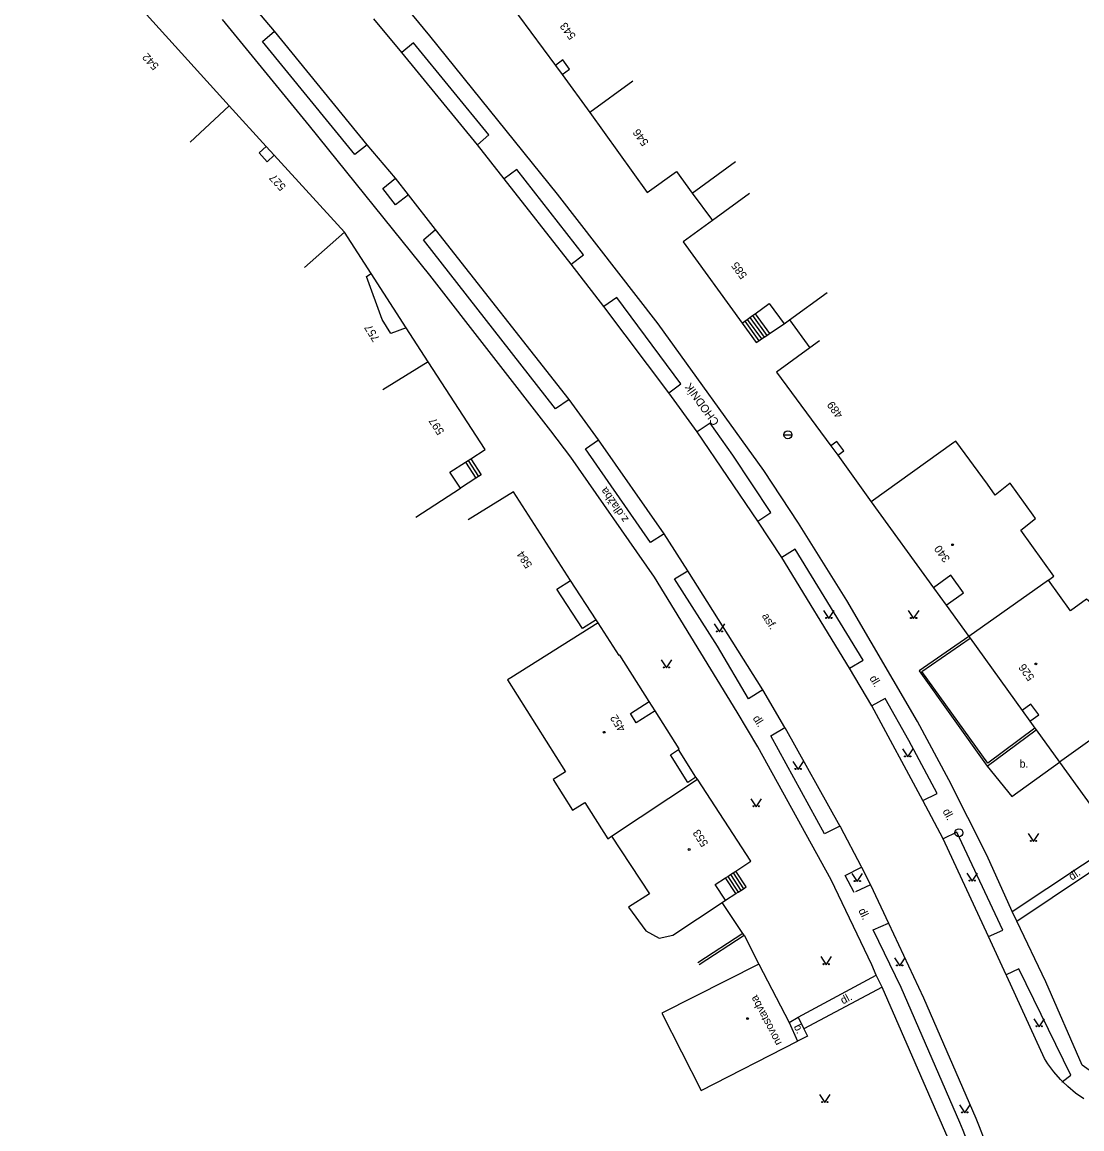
# Model space of a CAD drawing. Extents: x -536391 to -535419, y -1201788 to -1200779.
# Drawn here: x -535647.8 to -535548.5, y -1201544.3 to -1201440.5 of the extents above; entities that cross this region are included whole.
import ezdxf

# ---------------------------------------------------------------- set-up
doc = ezdxf.new("R2010")
doc.units = 0
for name, color, linetype in [('CIZÍ_NADZEM_POPIS', 7, 'Continuous'), ('CIZÍ_PODZEM', 7, 'Continuous'), ('CIZÍ_PODZEM_POPIS', 7, 'Continuous'), ('ELE_EON', 7, 'Continuous'), ('POL_ZNAČKA_PRACOVNÍ', 7, 'Continuous'), ('SDEL_EON', 7, 'Continuous'), ('SDEL_EON_POPIS', 7, 'Continuous'), ('TECH_OCHR_PÁSMO_HRAN', 7, 'Continuous'), ('ZP_EON', 7, 'Continuous')]:
    doc.layers.add(name, color=color, linetype=linetype)

msp = doc.modelspace()

# ---------------------------------------------------------------- linework, layer by layer
at = {"layer": 'CIZÍ_PODZEM'}
for centre in [(-535560.63, -1201489.51), (-535552.83, -1201500.69), (-535593.29, -1201507.09), (-535585.32, -1201518.08), (-535579.84, -1201533.93)]:
    msp.add_circle(centre, 0.0875, dxfattribs=at)
at = {"layer": 'CIZÍ_PODZEM_POPIS'}
msp.add_line((-535576.445, -1201479.21), (-535575.695, -1201479.21), dxfattribs=at)
for points in [[(-535585.02, -1201456.55), (-535583.14, -1201459.14)], [(-535575.91, -1201468.43), (-535574, -1201471.06)], [(-535559.12, -1201498.12), (-535563.78, -1201501.34), (-535557.38, -1201510.26), (-535552.8, -1201506.87)], [(-535552.92, -1201506.71), (-535557.33, -1201509.98), (-535563.5, -1201501.39), (-535559, -1201498.28)], [(-535580.3, -1201525.96), (-535582.22, -1201523.03)], [(-535580.3, -1201525.96), (-535584.49, -1201528.69)], [(-535584.38, -1201528.86), (-535580.16, -1201526.11), (-535580.3, -1201525.96)], [(-535580.16, -1201526.11), (-535578.8, -1201528.82)]]:
    msp.add_lwpolyline(points, dxfattribs=at)
msp.add_circle((-535576.07, -1201479.21), 0.375, dxfattribs=at)
at = {"layer": 'ELE_EON'}
for radius in [0.375, 0.0005]:
    msp.add_circle((-535560.04, -1201516.511), radius, dxfattribs=at)
at = {"layer": 'SDEL_EON'}
for points in [[(-535572.72, -1201495.68), (-535572.22, -1201496.43), (-535571.72, -1201495.68)], [(-535564.78, -1201495.68), (-535564.28, -1201496.43), (-535563.78, -1201495.68)], [(-535582.98, -1201496.94), (-535582.48, -1201497.69), (-535581.98, -1201496.94)], [(-535587.95, -1201500.31), (-535587.45, -1201501.06), (-535586.95, -1201500.31)], [(-535565.34, -1201508.65), (-535564.84, -1201509.4), (-535564.34, -1201508.65)], [(-535575.61, -1201509.83), (-535575.11, -1201510.58), (-535574.61, -1201509.83)], [(-535579.54, -1201513.32), (-535579.04, -1201514.07), (-535578.54, -1201513.32)], [(-535553.54, -1201516.57), (-535553.04, -1201517.32), (-535552.54, -1201516.57)], [(-535570.06, -1201520.34), (-535569.56, -1201521.09), (-535569.06, -1201520.34)], [(-535559.29, -1201520.29), (-535558.79, -1201521.04), (-535558.29, -1201520.29)], [(-535572.99, -1201528.12), (-535572.49, -1201528.87), (-535571.99, -1201528.12)], [(-535566.09, -1201528.24), (-535565.59, -1201528.99), (-535565.09, -1201528.24)], [(-535553.03, -1201533.94), (-535552.53, -1201534.69), (-535552.03, -1201533.94)], [(-535573.11, -1201541.05), (-535572.61, -1201541.8), (-535572.11, -1201541.05)], [(-535559.99, -1201542.01), (-535559.49, -1201542.76), (-535558.99, -1201542.01)]]:
    msp.add_lwpolyline(points, dxfattribs=at)
for centre in [(-535572.47, -1201496.38), (-535571.97, -1201496.38), (-535564.53, -1201496.38), (-535564.03, -1201496.38), (-535582.73, -1201497.64), (-535582.23, -1201497.64), (-535587.7, -1201501.01), (-535587.2, -1201501.01), (-535565.09, -1201509.35), (-535564.59, -1201509.35), (-535575.36, -1201510.53), (-535574.86, -1201510.53), (-535579.29, -1201514.02), (-535578.79, -1201514.02), (-535553.29, -1201517.27), (-535552.79, -1201517.27), (-535569.81, -1201521.04), (-535569.31, -1201521.04), (-535559.04, -1201520.99), (-535558.54, -1201520.99), (-535572.74, -1201528.82), (-535572.24, -1201528.82), (-535565.84, -1201528.94), (-535565.34, -1201528.94), (-535552.78, -1201534.64), (-535552.28, -1201534.64), (-535572.86, -1201541.75), (-535572.36, -1201541.75), (-535559.74, -1201542.71), (-535559.24, -1201542.71)]:
    msp.add_circle(centre, 0.05, dxfattribs=at)
at = {"layer": 'SDEL_EON_POPIS'}
for points in [[(-535603.63, -1201436.76), (-535597.84, -1201444.59)], [(-535628.43, -1201448.37), (-535636.18, -1201439.82)], [(-535597.22, -1201445.45), (-535596.52, -1201444.93), (-535597.16, -1201444.08), (-535597.84, -1201444.59)], [(-535597.84, -1201444.59), (-535597.22, -1201445.45)], [(-535597.22, -1201445.45), (-535594.64, -1201449.01)], [(-535590.58, -1201446.08), (-535594.64, -1201449.01)], [(-535628.43, -1201448.37), (-535632.07, -1201451.79)], [(-535624.94, -1201452.19), (-535628.43, -1201448.37)], [(-535594.64, -1201449.01), (-535589.26, -1201456.5), (-535586.5, -1201454.52), (-535585.02, -1201456.55)], [(-535624.19, -1201453.01), (-535624.85, -1201453.62), (-535625.61, -1201452.79), (-535624.94, -1201452.19)], [(-535624.19, -1201453.01), (-535624.94, -1201452.19)], [(-535617.62, -1201460.22), (-535624.19, -1201453.01)], [(-535585.02, -1201456.55), (-535580.97, -1201453.61)], [(-535579.65, -1201456.6), (-535583.14, -1201459.14)], [(-535583.14, -1201459.14), (-535585.89, -1201461.14), (-535580.35, -1201468.74)], [(-535617.62, -1201460.22), (-535621.36, -1201463.53)], [(-535615.13, -1201464.09), (-535617.62, -1201460.22)], [(-535611.83, -1201469.2), (-535613.28, -1201469.71), (-535614.09, -1201468.41), (-535615.54, -1201464.37), (-535615.13, -1201464.09)], [(-535611.83, -1201469.2), (-535615.13, -1201464.09)], [(-535575.91, -1201468.43), (-535572.39, -1201465.87)], [(-535579.14, -1201467.86), (-535577.82, -1201466.9), (-535576.43, -1201468.81)], [(-535579.38, -1201468.04), (-535579.14, -1201467.86)], [(-535580.35, -1201468.74), (-535580.11, -1201468.57)], [(-535580.11, -1201468.57), (-535579.87, -1201468.39)], [(-535579.87, -1201468.39), (-535579.62, -1201468.21)], [(-535579.62, -1201468.21), (-535579.38, -1201468.04)], [(-535576.43, -1201468.81), (-535575.91, -1201468.43)], [(-535609.77, -1201472.37), (-535611.83, -1201469.2)], [(-535574, -1201471.06), (-535577.13, -1201473.34), (-535572.04, -1201480.25)], [(-535573.09, -1201470.39), (-535574, -1201471.06)], [(-535609.77, -1201472.37), (-535614.02, -1201475)], [(-535605.77, -1201481.45), (-535604.43, -1201480.58), (-535609.77, -1201472.37)], [(-535571.38, -1201481.13), (-535570.82, -1201480.7), (-535571.48, -1201479.84), (-535572.04, -1201480.25)], [(-535572.04, -1201480.25), (-535571.38, -1201481.13)], [(-535571.38, -1201481.13), (-535568.27, -1201485.48)], [(-535606.75, -1201484.22), (-535607.73, -1201482.72), (-535606.27, -1201481.77)], [(-535606.27, -1201481.77), (-535606.02, -1201481.61)], [(-535606.02, -1201481.61), (-535605.77, -1201481.45)], [(-535610.94, -1201486.94), (-535606.75, -1201484.22)], [(-535596.43, -1201492.88), (-535601.78, -1201484.55), (-535606.03, -1201487.18)], [(-535568.27, -1201485.48), (-535562.42, -1201493.56)], [(-535561.25, -1201495.18), (-535559.62, -1201494.01), (-535560.8, -1201492.38), (-535562.42, -1201493.56)], [(-535594.02, -1201496.55), (-535595.31, -1201497.36), (-535597.73, -1201493.68), (-535596.43, -1201492.88)], [(-535594.02, -1201496.55), (-535596.43, -1201492.88)], [(-535562.42, -1201493.56), (-535561.25, -1201495.18)], [(-535561.25, -1201495.18), (-535559.12, -1201498.12)], [(-535593.84, -1201496.84), (-535594.02, -1201496.55)], [(-535589.05, -1201504.22), (-535591.81, -1201499.86), (-535591.89, -1201499.91), (-535593.84, -1201496.84)], [(-535559.12, -1201498.12), (-535559, -1201498.28)], [(-535559, -1201498.28), (-535554.1, -1201505.06)], [(-535588.51, -1201505.08), (-535590.27, -1201506.19), (-535590.81, -1201505.33), (-535589.05, -1201504.22)], [(-535588.51, -1201505.08), (-535589.05, -1201504.22)], [(-535586.31, -1201508.69), (-535586.24, -1201508.64), (-535588.51, -1201505.08)], [(-535553.38, -1201506.06), (-535552.56, -1201505.47), (-535553.29, -1201504.47), (-535554.1, -1201505.06)], [(-535554.1, -1201505.06), (-535553.38, -1201506.06)], [(-535553.38, -1201506.06), (-535552.92, -1201506.71)], [(-535552.92, -1201506.71), (-535552.8, -1201506.87)], [(-535552.8, -1201506.87), (-535550.61, -1201509.88)], [(-535584.69, -1201511.3), (-535585.45, -1201511.8), (-535587.08, -1201509.19), (-535586.31, -1201508.69)], [(-535584.69, -1201511.3), (-535586.31, -1201508.69)], [(-535550.61, -1201509.88), (-535545.22, -1201517.36), (-535542.59, -1201515.46), (-535539.52, -1201519.7)], [(-535584.55, -1201511.49), (-535584.69, -1201511.3)], [(-535580.95, -1201520.11), (-535579.53, -1201519.18), (-535584.55, -1201511.49)], [(-535581.92, -1201522.84), (-535582.88, -1201521.36), (-535581.92, -1201520.74)], [(-535581.92, -1201520.74), (-535581.7, -1201520.6)], [(-535581.7, -1201520.6), (-535581.45, -1201520.43)], [(-535581.45, -1201520.43), (-535581.2, -1201520.27)], [(-535581.2, -1201520.27), (-535580.95, -1201520.11)], [(-535582.22, -1201523.03), (-535581.92, -1201522.84)], [(-535578.8, -1201528.82), (-535575.96, -1201534.28), (-535575.17, -1201536.03)]]:
    msp.add_lwpolyline(points, dxfattribs=at)
at = {"layer": 'TECH_OCHR_PÁSMO_HRAN'}
for points in [[(-535575.08, -1201487.48), (-535578.32, -1201482.57), (-535588.21, -1201468.81), (-535597.64, -1201456.65), (-535609.61, -1201441.81), (-535625.68, -1201422.33), (-535639.79, -1201405.22), (-535649.04, -1201393.87), (-535654.09, -1201387.48), (-535663.33, -1201375.03), (-535670.67, -1201364.48), (-535678.2, -1201352.8), (-535684.64, -1201342.15), (-535696.74, -1201321.29), (-535703.13, -1201310.59)], [(-535624.17, -1201441.38), (-535626.81, -1201438.25)], [(-535588.58, -1201492.55), (-535596.39, -1201481.31), (-535598.27, -1201478.84), (-535609.61, -1201464.24), (-535620.89, -1201450.25), (-535629.06, -1201440.29)], [(-535612.25, -1201443.38), (-535614.85, -1201440.24)], [(-535615.48, -1201452.05), (-535616.66, -1201452.93), (-535625.31, -1201442.34), (-535624.17, -1201441.38)], [(-535615.48, -1201452.05), (-535624.17, -1201441.38)], [(-535605.16, -1201452.04), (-535604.1, -1201451.1), (-535611.16, -1201442.48), (-535612.25, -1201443.38)], [(-535605.16, -1201452.04), (-535612.25, -1201443.38)], [(-535612.84, -1201455.15), (-535615.48, -1201452.05)], [(-535602.64, -1201455.23), (-535605.16, -1201452.04)], [(-535596.38, -1201463.21), (-535595.22, -1201462.35), (-535601.47, -1201454.35), (-535602.64, -1201455.23)], [(-535611.62, -1201456.73), (-535612.83, -1201457.65), (-535614.02, -1201456.12), (-535612.84, -1201455.15)], [(-535611.62, -1201456.73), (-535612.84, -1201455.15)], [(-535596.38, -1201463.21), (-535602.64, -1201455.23)], [(-535609.08, -1201459.97), (-535611.62, -1201456.73)], [(-535596.57, -1201475.91), (-535597.83, -1201476.77), (-535610.22, -1201460.94), (-535609.08, -1201459.97)], [(-535596.57, -1201475.91), (-535609.08, -1201459.97)], [(-535593.31, -1201467.2), (-535596.38, -1201463.21)], [(-535587.22, -1201475.27), (-535586.09, -1201474.42), (-535592.1, -1201466.35), (-535593.31, -1201467.2)], [(-535587.22, -1201475.27), (-535593.31, -1201467.2)], [(-535579.14, -1201467.86), (-535577.78, -1201469.72)], [(-535580.35, -1201468.74), (-535579.03, -1201470.56), (-535578.78, -1201470.39)], [(-535580.11, -1201468.57), (-535578.78, -1201470.39)], [(-535579.87, -1201468.39), (-535578.53, -1201470.22)], [(-535579.62, -1201468.21), (-535578.28, -1201470.05)], [(-535579.38, -1201468.04), (-535578.03, -1201469.89)], [(-535577.78, -1201469.72), (-535576.43, -1201468.81)], [(-535578.28, -1201470.05), (-535578.03, -1201469.89)], [(-535578.03, -1201469.89), (-535577.78, -1201469.72)], [(-535578.78, -1201470.39), (-535578.53, -1201470.22)], [(-535578.53, -1201470.22), (-535578.28, -1201470.05)], [(-535593.82, -1201479.68), (-535596.57, -1201475.91)], [(-535584.56, -1201478.93), (-535587.22, -1201475.27)], [(-535578.87, -1201487.3), (-535577.65, -1201486.49), (-535581.22, -1201481.13), (-535583.35, -1201478.13), (-535584.56, -1201478.93)], [(-535578.87, -1201487.3), (-535584.56, -1201478.93)], [(-535587.67, -1201488.49), (-535588.95, -1201489.29), (-535595.03, -1201480.53), (-535593.82, -1201479.68)], [(-535587.67, -1201488.49), (-535593.82, -1201479.68)], [(-535606.27, -1201481.77), (-535605.3, -1201483.28)], [(-535606.02, -1201481.61), (-535605.05, -1201483.11)], [(-535605.77, -1201481.45), (-535604.8, -1201482.95), (-535605.05, -1201483.11)], [(-535605.3, -1201483.28), (-535606.75, -1201484.22)], [(-535605.05, -1201483.11), (-535605.3, -1201483.28)], [(-535576.64, -1201490.71), (-535578.87, -1201487.3)], [(-535555.04, -1201523.88), (-535557.42, -1201518.6), (-535560.98, -1201511.54), (-535563.92, -1201506.08), (-535570.55, -1201494.73), (-535575.08, -1201487.48)], [(-535585.45, -1201491.95), (-535587.67, -1201488.49)], [(-535570.28, -1201501.09), (-535569.02, -1201500.34), (-535575.39, -1201489.94), (-535576.64, -1201490.71)], [(-535570.28, -1201501.09), (-535576.64, -1201490.71)], [(-535559.28, -1201549.57), (-535559.59, -1201548.75), (-535561.04, -1201545.16), (-535567.24, -1201530.99), (-535567.78, -1201529.85), (-535568.21, -1201528.88), (-535572, -1201520.91), (-535578.88, -1201508.46), (-535580.82, -1201505.2), (-535588.58, -1201492.55)], [(-535578.4, -1201503.1), (-535579.76, -1201503.95), (-535582.65, -1201499.03), (-535586.68, -1201492.71), (-535585.45, -1201491.95)], [(-535578.4, -1201503.1), (-535585.45, -1201491.95)], [(-535568.2, -1201504.62), (-535570.28, -1201501.09)], [(-535576.34, -1201506.64), (-535578.4, -1201503.1)], [(-535563.41, -1201513.48), (-535562.09, -1201512.83), (-535564.73, -1201507.85), (-535566.94, -1201503.92), (-535568.2, -1201504.62)], [(-535563.41, -1201513.48), (-535568.2, -1201504.62)], [(-535571.19, -1201515.88), (-535572.62, -1201516.6), (-535577.66, -1201507.41), (-535576.34, -1201506.64)], [(-535576.34, -1201506.64), (-535571.19, -1201515.88)], [(-535557.38, -1201510.26), (-535555.08, -1201513.12), (-535550.61, -1201509.88)], [(-535561.52, -1201517.09), (-535563.41, -1201513.48)], [(-535571.19, -1201515.88), (-535571.13, -1201515.99), (-535569.22, -1201519.6), (-535569.16, -1201519.73)], [(-535557.26, -1201526.23), (-535555.94, -1201525.63), (-535560.22, -1201516.46), (-535561.52, -1201517.09)], [(-535557.26, -1201526.23), (-535561.52, -1201517.09)], [(-535555.04, -1201523.88), (-535545.22, -1201517.36)], [(-535554.6, -1201524.8), (-535544.59, -1201518.09), (-535542.21, -1201521.62)], [(-535569.87, -1201522.11), (-535570.69, -1201520.51), (-535569.16, -1201519.73)], [(-535569.16, -1201519.73), (-535568.34, -1201521.39)], [(-535580.95, -1201522.21), (-535581.92, -1201520.74)], [(-535581.7, -1201520.6), (-535580.74, -1201522.07)], [(-535581.45, -1201520.43), (-535580.49, -1201521.91)], [(-535581.2, -1201520.27), (-535580.24, -1201521.75)], [(-535580.24, -1201521.75), (-535579.99, -1201521.58), (-535580.95, -1201520.11)], [(-535580.49, -1201521.91), (-535580.24, -1201521.75)], [(-535568.34, -1201521.39), (-535569.73, -1201522.04)], [(-535568.34, -1201521.39), (-535566.65, -1201524.99)], [(-535581.92, -1201522.84), (-535580.95, -1201522.21)], [(-535580.95, -1201522.21), (-535580.74, -1201522.07)], [(-535580.74, -1201522.07), (-535580.49, -1201521.91)], [(-535554.6, -1201524.8), (-535555.04, -1201523.88)], [(-535568.06, -1201525.62), (-535566.65, -1201524.99)], [(-535566.65, -1201524.99), (-535563.37, -1201531.99), (-535558.46, -1201543.26), (-535558.14, -1201544.05), (-535556.54, -1201548.16)], [(-535533.37, -1201535.56), (-535539.82, -1201539.32), (-535539.9, -1201539.36), (-535540.68, -1201539.65), (-535541.47, -1201539.86), (-535542.29, -1201540), (-535543.11, -1201540.06), (-535543.94, -1201540.03), (-535544.76, -1201539.93), (-535545.56, -1201539.75), (-535546.35, -1201539.49), (-535547.1, -1201539.16), (-535547.82, -1201538.75), (-535548.5, -1201538.28), (-535551.9, -1201530.48), (-535554.6, -1201524.8)], [(-535557.96, -1201548.78), (-535558.09, -1201548.43), (-535559.64, -1201544.42), (-535559.94, -1201543.67), (-535565.46, -1201531.02), (-535568.06, -1201525.62)], [(-535555.61, -1201529.83), (-535557.26, -1201526.23)], [(-535575.96, -1201534.28), (-535575.11, -1201533.79), (-535567.78, -1201529.85)], [(-535550.33, -1201539.83), (-535549.54, -1201539.23), (-535554.43, -1201529.26), (-535555.61, -1201529.83)], [(-535550.33, -1201539.83), (-535550.53, -1201539.64), (-535551.15, -1201538.92), (-535551.71, -1201538.16), (-535552.02, -1201537.67), (-535555.55, -1201529.95), (-535555.61, -1201529.83)], [(-535567.24, -1201530.99), (-535574.57, -1201534.88), (-535574.24, -1201535.57), (-535575.17, -1201536.03)], [(-535575.11, -1201533.79), (-535574.57, -1201534.88)], [(-535550.38, -1201539.87), (-535550.33, -1201539.83)], [(-535548.32, -1201541.43), (-535549.11, -1201540.9), (-535549.84, -1201540.3), (-535550.33, -1201539.83)]]:
    msp.add_lwpolyline(points, dxfattribs=at)
at = {"layer": 'ZP_EON'}
for points in [[(-535551.65, -1201492.83), (-535551.14, -1201492.47), (-535554.25, -1201488.16), (-535552.86, -1201487.04), (-535553.07, -1201486.75), (-535555.24, -1201483.74), (-535556.63, -1201484.86), (-535557.37, -1201483.85), (-535560.34, -1201479.81), (-535560.52, -1201479.94), (-535568.27, -1201485.48)], [(-535543.17, -1201504.58), (-535545.22, -1201501.82), (-535543.66, -1201500.66), (-535545.15, -1201497.07), (-535548.08, -1201494.6), (-535549.58, -1201495.71), (-535551.65, -1201492.83), (-535559.12, -1201498.12)], [(-535593.84, -1201496.84), (-535602.03, -1201502), (-535602.34, -1201502.19), (-535596.91, -1201510.8), (-535598.05, -1201511.52), (-535596.25, -1201514.39), (-535595.1, -1201513.67), (-535592.95, -1201517.08), (-535592.58, -1201516.84), (-535584.55, -1201511.49)], [(-535533.86, -1201516), (-535536.09, -1201512.79), (-535536.93, -1201513.39), (-535540.05, -1201508.98), (-535530.66, -1201502.35), (-535533.84, -1201498.06), (-535543.17, -1201504.58), (-535550.61, -1201509.88)], [(-535592.58, -1201516.84), (-535589.04, -1201522.22), (-535590.99, -1201523.49), (-535589.38, -1201525.7), (-535588.14, -1201526.4), (-535586.84, -1201526.12), (-535582.22, -1201523.03)], [(-535578.8, -1201528.82), (-535587.87, -1201533.43), (-535584.2, -1201540.65), (-535575.17, -1201536.03)]]:
    msp.add_lwpolyline(points, dxfattribs=at)

# ---------------------------------------------------------------- texts
at = {"layer": 'CIZÍ_NADZEM_POPIS'}
for s, rotation, p in [('543', 126.43998, (-535595.89, -1201441.83)), ('542', 132.15002, (-535634.95, -1201444.61)), ('546', 125.64999, (-535589.07, -1201451.81)), ('527', 132.32999, (-535623.05, -1201455.93)), ('585', 126.00998, (-535579.84, -1201464.27)), ('757', 121.76998, (-535614.28, -1201470.2)), ('489', 126.28998, (-535570.86, -1201477.33)), ('597', 122.96998, (-535608.23, -1201478.91)), ('340', 125.87997, (-535560.83, -1201490.83)), ('584', 122.66998, (-535599.98, -1201491.42)), ('526', 125.81998, (-535552.92, -1201501.94)), ('452', 122.13002, (-535591.24, -1201506.77)), ('553', 123.05999, (-535583.49, -1201517.52))]:
    msp.add_text(s, height=0.75, rotation=rotation, dxfattribs=at).set_placement(p)
at = {"layer": 'POL_ZNAČKA_PRACOVNÍ'}
for s, rotation, p in [('CHODNÍK', 126.02, (-535582.46, -1201478.01)), ('z.dlažba', 124.76001, (-535590.96, -1201487.12)), ('asf.', 302.29998, (-535578.53, -1201496.18)), ('dl.', 300.51, (-535568.45, -1201502.02)), ('dl.', 302.52, (-535579.39, -1201505.78)), ('dl.', 297.62997, (-535561.59, -1201514.48)), ('dl.', 33.83998, (-535549.45, -1201521.01)), ('dl.', 295.42999, (-535569.48, -1201523.79)), ('novostavba', 117.48001, (-535576.61, -1201536.21)), ('dl.', 27.95003, (-535570.9, -1201532.61)), ('b.', 295.89002, (-535575.54, -1201534.66))]:
    msp.add_text(s, height=0.75, rotation=rotation, dxfattribs=at).set_placement(p)
msp.add_text('b.', height=0.75, dxfattribs=at).set_placement((-535554.36, -1201510.41))

doc.saveas('drawing.dxf')
